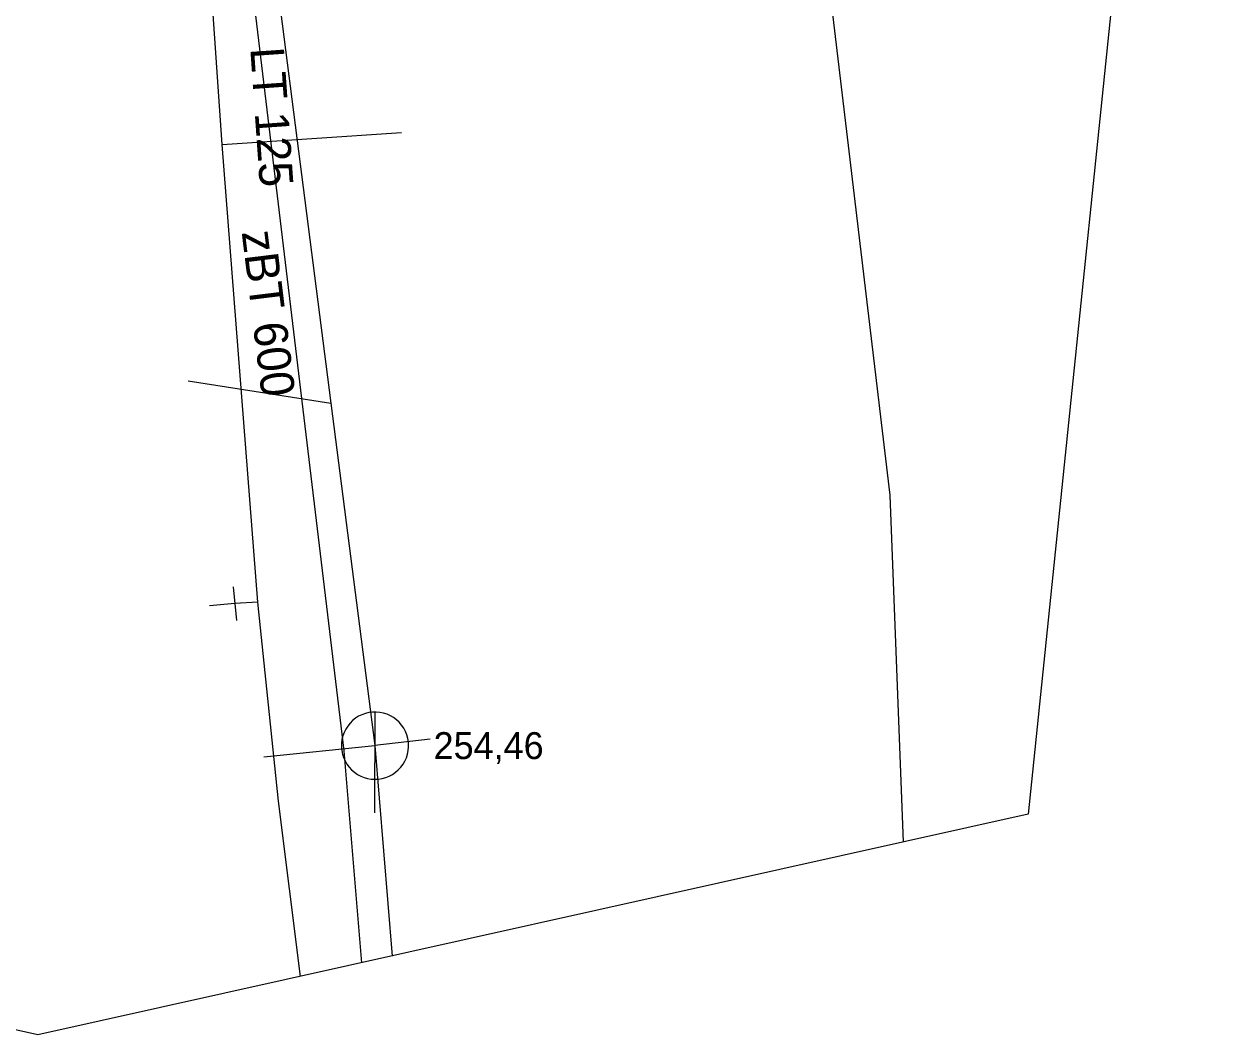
# Model space of a CAD drawing. Extents: x -725807 to -725723.1, y -978165.9 to -978101.2.
# Drawn here: x -725758.99 to -725723.13, y -978165.91 to -978135.86 of the extents above; entities that cross this region are included whole.
import ezdxf

# ---------------------------------------------------------------- set-up
doc = ezdxf.new("R2010")
doc.units = 0
for name, color, linetype in [('Vrstva 1', 7, 'Continuous'), ('Vrstva 11', 7, 'Continuous'), ('Vrstva 13', 7, 'Continuous'), ('Vrstva 14', 7, 'Continuous'), ('Vrstva 17', 7, 'Continuous'), ('Vrstva 22', 7, 'Continuous'), ('Vrstva 34', 7, 'Continuous')]:
    doc.layers.add(name, color=color, linetype=linetype)

msp = doc.modelspace()

# ---------------------------------------------------------------- linework, layer by layer
at = {"layer": 'Vrstva 1'}
msp.add_lwpolyline([(-725807.01, -978138.838), (-725796.543, -978102.971), (-725723.134, -978101.157), (-725729.135, -978159.354), (-725758.583, -978165.913), (-725792.915, -978158.237)], close=True, dxfattribs=at)
at = {"layer": 'Vrstva 11'}
for points in [[(-725754.119, -978146.465), (-725749.869, -978147.131)], [(-725746.921, -978157.12), (-725748.559, -978157.311)], [(-725751.868, -978157.645), (-725748.559, -978157.311)]]:
    msp.add_lwpolyline(points, dxfattribs=at)
at = {"layer": 'Vrstva 13'}
for points in [[(-725753.106, -978139.436), (-725747.766, -978139.074)], [(-725752.728, -978153.089), (-725753.478, -978153.157)], [(-725752.044, -978153.046), (-725752.728, -978153.089)]]:
    msp.add_lwpolyline(points, dxfattribs=at)
at = {"layer": 'Vrstva 14'}
for points in [[(-725735.431, -978131.559), (-725733.245, -978149.864), (-725732.85, -978160.181)], [(-725751.66, -978133.208), (-725749.869, -978147.131), (-725748.559, -978157.311)], [(-725748.559, -978157.311), (-725748.053, -978163.568)]]:
    msp.add_lwpolyline(points, dxfattribs=at)
at = {"layer": 'Vrstva 17'}
for points in [[(-725750.778, -978164.175), (-725751.43, -978158.967), (-725752.044, -978153.046), (-725753.105, -978139.436), (-725754.02, -978126.231)], [(-725748.949, -978163.767), (-725749.477, -978157.465), (-725752.379, -978133.28), (-725750.701, -978126.719)]]:
    msp.add_lwpolyline(points, dxfattribs=at)
at = {"layer": 'Vrstva 22'}
for points in [[(-725747.559, -978157.312), (-725747.564, -978157.203), (-725747.582, -978157.095), (-725747.612, -978156.989), (-725747.652, -978156.888), (-725747.704, -978156.791), (-725747.766, -978156.701), (-725747.838, -978156.618), (-725747.918, -978156.544), (-725748.006, -978156.478), (-725748.1, -978156.423), (-725748.2, -978156.378), (-725748.305, -978156.345), (-725748.412, -978156.323), (-725748.521, -978156.313), (-725748.631, -978156.315), (-725748.739, -978156.329), (-725748.846, -978156.354), (-725748.949, -978156.391), (-725749.047, -978156.44), (-725749.139, -978156.498), (-725749.225, -978156.567), (-725749.302, -978156.644), (-725749.371, -978156.73), (-725749.43, -978156.822), (-725749.478, -978156.92), (-725749.515, -978157.023), (-725749.541, -978157.13), (-725749.555, -978157.238), (-725749.558, -978157.348), (-725749.548, -978157.457), (-725749.527, -978157.564), (-725749.493, -978157.668), (-725749.449, -978157.768), (-725749.394, -978157.863), (-725749.328, -978157.951), (-725749.254, -978158.031), (-725749.171, -978158.103), (-725749.081, -978158.165), (-725748.985, -978158.217), (-725748.883, -978158.258), (-725748.778, -978158.288), (-725748.67, -978158.306), (-725748.56, -978158.312), (-725748.451, -978158.306), (-725748.343, -978158.288), (-725748.238, -978158.259), (-725748.136, -978158.218), (-725748.039, -978158.166), (-725747.949, -978158.104), (-725747.866, -978158.033), (-725747.791, -978157.953), (-725747.726, -978157.865), (-725747.67, -978157.771), (-725747.626, -978157.671), (-725747.592, -978157.567), (-725747.57, -978157.459), (-725747.56, -978157.35), (-725747.559, -978157.312)], [(-725748.559, -978159.312), (-725748.558, -978156.312)]]:
    msp.add_lwpolyline(points, dxfattribs=at)
at = {"layer": 'Vrstva 34'}
msp.add_lwpolyline([(-725752.777, -978152.591), (-725752.679, -978153.586)], dxfattribs=at)

# ---------------------------------------------------------------- texts
at = {"layer": 'Vrstva 1'}
for s, rotation, p in [('LT 125', 274, (-725752.269, -978136.573)), ('zBT 600 ', 277, (-725752.525, -978142.041))]:
    msp.add_text(s, height=1, rotation=rotation, dxfattribs=at).set_placement(p)
msp.add_text('254,46', height=0.8, dxfattribs=at).set_placement((-725746.816, -978157.711))

doc.saveas('drawing.dxf')
